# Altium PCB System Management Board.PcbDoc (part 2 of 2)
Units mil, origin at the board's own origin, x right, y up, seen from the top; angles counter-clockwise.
Board outline 5905.51 x 4330.71 mil, 4 copper layers (F.Cu, In1.Cu, In2.Cu, B.Cu); 241 components, 148 nets, 704 pads, 16 vias.
Unrouted connection lines stored in the file: 314.
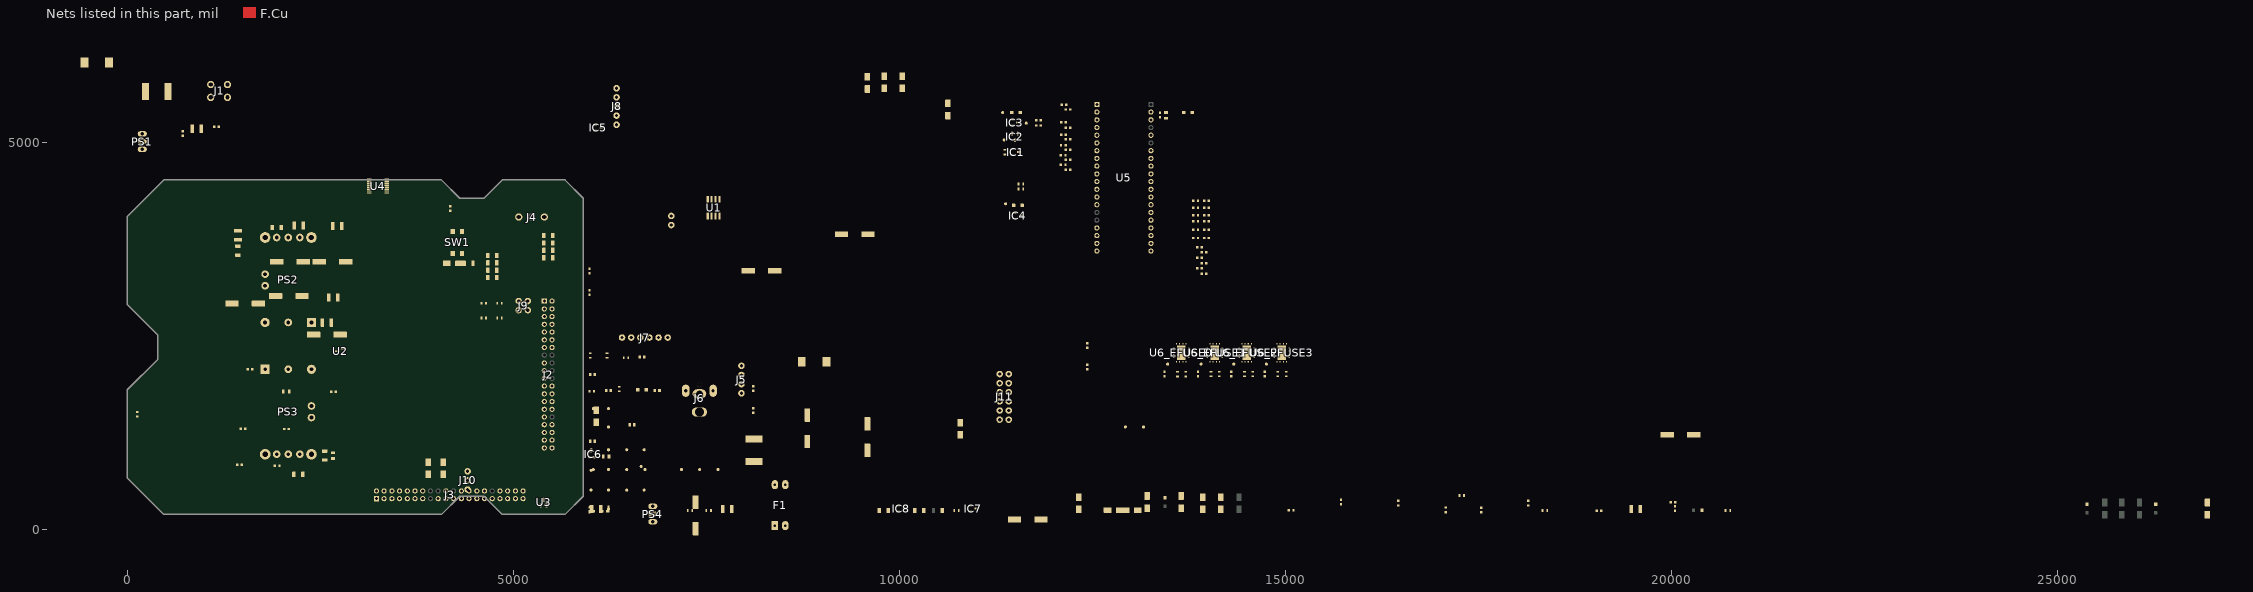
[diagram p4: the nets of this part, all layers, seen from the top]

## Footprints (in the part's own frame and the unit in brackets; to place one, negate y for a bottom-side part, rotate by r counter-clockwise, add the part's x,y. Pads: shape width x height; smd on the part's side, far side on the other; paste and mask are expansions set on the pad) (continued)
PINHEADER_2X20_P2.54MM_HORIZONTAL [mm]
  rect 1.7x1.7 hole 1 paste-2539.97 mask+0: 1(0,0)
  rrect100% 1.7x1.7 hole 1 paste-2539.97 mask+0: 2(2.54,0) 3(0,-2.54) 4(2.54,-2.54) 5(0,-5.08) 6(2.54,-5.08) 7(0,-7.62) 8(2.54,-7.62) 9(0,-10.16) 10(2.54,-10.16) 11(0,-12.7) 12(2.54,-12.7) 13(0,-15.24) 14(2.54,-15.24) 15(0,-17.78) 16(2.54,-17.78) 17(0,-20.32) 18(2.54,-20.32) 19(0,-22.86) 20(2.54,-22.86) 21(0,-25.4) 22(2.54,-25.4) 23(0,-27.94) 24(2.54,-27.94) 25(0,-30.48) 26(2.54,-30.48) 27(0,-33.02) 28(2.54,-33.02) 29(0,-35.56) 30(2.54,-35.56) 31(0,-38.1) 32(2.54,-38.1) 33(0,-40.64) 34(2.54,-40.64) 35(0,-43.18) 36(2.54,-43.18) 37(0,-45.72) 38(2.54,-45.72) 39(0,-48.26) 40(2.54,-48.26)
  silkscreen extent -1.27,-49.59 12.64,1.33, body extent -1.14,-59.18 22.16,10.92, height 8.5
PinHeader_2x20_P2.54mm_Vertical [mm]
  rect 1.7x1.7 hole 1 paste-2539.97 mask+0: 1(0,0)
  rrect100% 1.7x1.7 hole 1 paste-2539.97 mask+0: 2(2.54,0) 3(0,-2.54) 4(2.54,-2.54) 5(0,-5.08) 6(2.54,-5.08) 7(0,-7.62) 8(2.54,-7.62) 9(0,-10.16) 10(2.54,-10.16) 11(0,-12.7) 12(2.54,-12.7) 13(0,-15.24) 14(2.54,-15.24) 15(0,-17.78) 16(2.54,-17.78) 17(0,-20.32) 18(2.54,-20.32) 19(0,-22.86) 20(2.54,-22.86) 21(0,-25.4) 22(2.54,-25.4) 23(0,-27.94) 24(2.54,-27.94) 25(0,-30.48) 26(2.54,-30.48) 27(0,-33.02) 28(2.54,-33.02) 29(0,-35.56) 30(2.54,-35.56) 31(0,-38.1) 32(2.54,-38.1) 33(0,-40.64) 34(2.54,-40.64) 35(0,-43.18) 36(2.54,-43.18) 37(0,-45.72) 38(2.54,-45.72) 39(0,-48.26) 40(2.54,-48.26)
  silkscreen extent -1.33,-49.59 3.87,1.33
R_0603 [mm]
  rect 0.6x0.9 smd: 1(-0.75,0) 2(0.75,0)
  silkscreen extent -1.3,-0.7 1.3,0.7, body extent -0.8,-0.4 0.75,0.4, height 0.44
R_1206_3216Metric [mm]
  rrect22% 1.125x1.75 smd mask+0: 1(-1.462,0) 2(1.462,0)
  silkscreen extent -0.73,-0.91 0.73,0.91
R_1206_3216METRIC [mm]
  rrect22% 1.125x1.75 smd mask+0: 1(-1.462,0) 2(1.462,0)
  silkscreen extent -0.73,-0.91 0.73,0.91
SMAZ36-13-F [mm]
  rect 2.5x1.7 smd: A(-2,0) K(2,0)
  silkscreen extent -3.9,-1.1 3.5,1.1, body extent -2.6,-1.3 2.6,1.3, height 2.4
SOT95P237X112-3N [mm]
  rect 1.3x0.6 smd: 1(-1.05,0.95) 2(-1.05,-0.95) 3(1.05,0)
  silkscreen extent -1.7,-1.46 0.05,1.5
SOT-23 [mm]
  rrect25% 1.475x0.6 smd mask+0: 1(-0.937,0.95) 2(-0.937,-0.95) 3(0.937,0)
  silkscreen extent -1.68,-1.56 0.65,1.56
SW_TL3305BF260QG [mm]
  rect 1.6x1.4 smd mask+0: 1(-3.6,-1.5) 1(3.6,-1.5) 2(-3.6,1.5) 2(3.6,1.5)
  silkscreen extent -5.1,-2.25 2.25,2.25, body extent -3.72,-2.25 3.78,2.25, height 5
TestPoint_Pad_D1.0mm [mm]
  round 1 smd paste-1 mask+0: 1(0,0)
  silkscreen extent -0.7,-0.7 0.7,0.7
TSSOP-16_4.4x5mm_P0.65mm [mm]
  rrect25% 1.475x0.4 smd mask+0: 1(-2.863,2.275) 2(-2.863,1.625) 3(-2.863,0.975) 4(-2.863,0.325) 5(-2.863,-0.325) 6(-2.863,-0.975) 7(-2.863,-1.625) 8(-2.863,-2.275) 9(2.863,-2.275) 10(2.863,-1.625) 11(2.863,-0.975) 12(2.863,-0.325) 13(2.863,0.325) 14(2.863,0.975) 15(2.863,1.625) 16(2.863,2.275)
  silkscreen extent -3.6,-2.74 2.2,2.74

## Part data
C1: "Ceramic Capacitor, Multilayer, Ceramic, 63V, 10% +Tol, 10% -Tol, X7R, 15% TC, 10uF, Surface Mount, 1210", Capacitor Type=Ceramic, Case/Package=1210, Manufacturer=Samsung, Manufacturer Part Number=CL32B106KMVNNWE, Max Operating Temperature=125°C, Min Operating Temperature=-55°C, Package Shape=Rectangular, Rated DC Voltage (URdc)=63V, Supplier Part Number=1276-7053-1-ND, Temperature Characteristics Code=X7R, Tolerance  (fill in as +-)=10%
C2 C4 C25 C26 C27 C28 C29 C31 C33 C34: "Ceramic Capacitor, Multilayer, Ceramic, 100V, 10% +Tol, 10% -Tol, X7R, 15% TC, 0.1uF, Surface Mount, 0603", Capacitor Type=Ceramic, Case/Package=0603, Manufacturer=Samsung, Max Operating Temperature=125°C, Min Operating Temperature=-55°C, Package Shape=Rectangular, Rated DC Voltage (URdc)=100V, Supplier Part Number=1276-6807-1-ND, Temperature Characteristics Code=X7R, Tolerance  (fill in as +-)=10%
C3 C30 C32 C35: "Ceramic Capacitor, Multilayer, Ceramic, 10V, 10% +Tol, 10% -Tol, X7R, 15% TC, 10uF, Surface Mount, 0805", Capacitor Type=Ceramic, Case/Package=0805, Manufacturer=Samsung, Max Operating Temperature=125°C, Min Operating Temperature=-55°C, Package Shape=Rectangular, Rated DC Voltage (URdc)=10V, Supplier Part Number=1276-2934-1-ND, Temperature Characteristics Code=X7R, Tolerance  (fill in as +-)=10%
C5 C9 C10 C14 C15 C19 C20 C24: library part C, "Ceramic Capacitor, Multilayer, Ceramic, 63V, 10% +Tol, 10% -Tol, X7R, 15% TC, 10uF, Surface Mount, 1210", Capacitor Type=Ceramic, Case/Package=1210, Manufacturer=Samsung, Manufacturer Part Number=CL32B106KMVNNWE, Max Operating Temperature=125°C, Min Operating Temperature=-55°C, Package Shape=Rectangular, Rated DC Voltage (URdc)=63V, Supplier Part Number=1276-7053-1-ND, Temperature Characteristics Code=X7R, Tolerance  (fill in as +-)=10%
C6 C7 C8 C11 C12 C13 C16 C17 C18 C21 C22 C23: library part C_Polarized, Voltage=63V
D1 D2 D10_EFUSE0 D10_EFUSE1 D10_EFUSE2 D10_EFUSE3 D28: "Led Red Diffused 0603 SMD", Manufacturer=Inolux, Supplier Part Number=3147-B1931USD-20D000814U1930CT-ND
D3 D4 D5 D26: "Led Green Diffused 0603 SMD", Manufacturer=Inolux, Supplier Part Number=3147-B1931NG--20D001114U1930CT-ND
D6 D7: library part D
D8 D9 D23 D24 D25 D32: library part D, "Rectifier Diode, Schottky, 1 Phase, 1 Element, 1A, 40V V(RRM), Silicon", Manufacturer=MCC, Manufacturer Part Number=SM5819PL-TP, Max Operating Temperature=125°C, Max Output current=1A, Max Power Dissipation=1.14W, Min Operating Temperature=-65°C, Non-rep Pk Forward Current-Max=30A, Package Body Material=Plastic, Package Shape=Rectangular, Package Style="SMALL OUTLINEMeter", Peak Reflow Temperature (Cel)=260°C, Rep Pk Reverse Voltage-Max=40V, Supplier Part Number=SM5819PL-TPMSCT-ND, Time @ Peak Reflow Temperature-Max (s)=10s
D12 D13 D14 D15 D16 D17 D18 D19 D30 D33 D34 D35 D36 D37 D38 D39: library part D_TVS, "Trans Voltage Suppressor Diode, 400W, 51V V(RWM), Bidirectional, 1 Element, Silicon, DO-214AC", Breakdown Voltage-Nom=59.7V, Clamping Voltage-Max=82.4V, Manufacturer=Littelfuse, Manufacturer Part Number=SMAJ51CA, Max Breakdown Voltage=62.7V, Max Operating Temperature=150°C, Min Breakdown Voltage=56.7V, Min Operating Temperature=-65°C, Non-rep Peak Rev Power Dis-Max=400W, Package Body Material=Plastic, Package Shape=Rectangular, Package Style="SMALL OUTLINEMeter", Peak Reflow Temperature (Cel)=260°C, Rep Pk Reverse Voltage-Max=51V, Supplier Part Number=SMAJ51CALFCT-ND, Time @ Peak Reflow Temperature-Max (s)=40s
D20 D21 D22 D31: "Zener Diode, 36V V(Z), 5%, 1W, Silicon, Unidirectional", Manufacturer=Diodes, Max Operating Temperature=150°C, Max Power Dissipation=1W, Min Operating Temperature=-65°C, Package Body Material=Plastic, Package Shape=Rectangular, Package Style="SMALL OUTLINEMeter", Peak Reflow Temperature (Cel)=260°C, Reference Voltage-Nom=36V, Supplier Part Number=SMAZ36-FDICT-ND, Test Current=10mA, Time @ Peak Reflow Temperature-Max (s)=40s, Voltage Tol-Max=5%
D27: "Led Yellow Clear 1608 SMD", Manufacturer=Inolux, Supplier Part Number=3147-B1931UY--20D000114U1930CT-ND
D29: "Led Blue Clear 1608 SMD", Manufacturer=Inolux, Supplier Part Number=3147-B1931NB--20C007614U1930CT-ND
F1: library part 3557-10, "Holder; Fuse; Auto Blade; 30A; PC Pin Terminal; Nylon Holder; Red", Manufacturer="Keystone Electronics", Supplier Part Number=36-3557-10-ND
F2 F10: "PTC Resettable Fuse, 33V, 0.04ohm, Surface Mount", Manufacturer=Bel, Max Operating Temperature=85°C, Min Operating Temperature=-40°C, Package Shape=Rectangular, Power=1.5W, Resistor Type="PTC THERMISTOR", Supplier Part Number=5923-0ZCF0185FF2CCT-ND
F3 F4: library part Fuse, "Fuse Chip Medium Time Delay Acting 25A 250V SMD Solder Pad 3912 9.8 X 3.05 X 4.06mm Ceramic", Case/Package=SMD/SMT, DC Cold Resistance=1.9mR, Manufacturer=Bel, Manufacturer Part Number=0678L9250-02, Max Operating Temperature=125°C, Min Operating Temperature=-55°C, Supplier Part Number=5923-0678L9250-02CT-ND, Voltage Rating (AC)=250V, Voltage Rating (DC)=72V
F5 F6 F7: "Electric Fuse, Fast Blow, 0.1A, 32VAC, 32VDC, Surface Mount", Current Rating=100mA, Manufacturer="Kyocera AVX", Max Operating Temperature=125°C, Min Operating Temperature=-55°C, Supplier Part Number=478-6872-1-ND
F8 F9 F11: library part F0603E0R50FSTR, "Electric Fuse, Fast Blow, 0.5A, 32VAC, 32VDC, 50A (IR), Surface Mount, 0603", Current Rating=500mA, Manufacturer="Kyocera AVX", Manufacturer Series=F0603E, Supplier Part Number=478-2860-1-ND, Voltage Rating (AC)=32V
IC1 IC2 IC3 IC4: "Small Signal Field-Effect Transistor, 5.6A I(D), 40V, 1-Element, N-Channel, Silicon, Metal-oxide Semiconductor FET, TO-236AB", Drain Current-Max (Abs) (ID)=5.6A, Drain-source On Resistance-Max=42mR, DS Breakdown Voltage-Min=40V, Manufacturer="Vishay Siliconix", MANUFACTURER_NAME=Vishay, Max Operating Temperature=150°C, Min Operating Temperature=-55°C, Operating Mode="ENHANCEMENT MODE", Package Body Material=Plastic, Package Shape=Rectangular, Package Style="SMALL OUTLINEMeter", Peak Reflow Temperature (Cel)=260°C, Power Dissipation-Max (Abs)=2.1W, Supplier Part Number=SI2318CDS-T1-GE3CT-ND, Time @ Peak Reflow Temperature-Max (s)=30s
IC5 IC6 IC7 IC8: library part SI2318CDS-T1-GE3, "Small Signal Field-Effect Transistor, 5.6A I(D), 40V, 1-Element, N-Channel, Silicon, Metal-oxide Semiconductor FET, TO-236AB", Drain Current-Max (Abs) (ID)=5.6A, Drain-source On Resistance-Max=42mR, DS Breakdown Voltage-Min=40V, Manufacturer="Vishay Siliconix", MANUFACTURER_NAME=Vishay, Max Operating Temperature=150°C, Min Operating Temperature=-55°C, Operating Mode="ENHANCEMENT MODE", Package Body Material=Plastic, Package Shape=Rectangular, Package Style="SMALL OUTLINEMeter", Peak Reflow Temperature (Cel)=260°C, Power Dissipation-Max (Abs)=2.1W, Supplier Part Number=SI2318CDS-T1-GE3CT-ND, Time @ Peak Reflow Temperature-Max (s)=30s
J1: "Rectangular Power Connector, 4 Contact(s), Male, Solder Terminal, Plug", Contact Resistance=10mR, Dielectric Withstanding Voltage (AC)=1.5kV, Flammability Rating="UL94 V-2", Insulation Resistance=1GR, Manufacturer=Molex, Max Operating Temperature=105°C, Min Operating Temperature=-40°C, Rated Current (Signal)=8A, Supplier Part Number=WM3844-ND
J2 J3: library part Conn_02x20_Odd_Even
J4: "Rectangular Power Connector, 3 Contact(s), Male, Solder Terminal, Plug", Contact Resistance=10mR, Dielectric Withstanding Voltage (AC)=1.5kV, Flammability Rating="UL94 V-2", Insulation Resistance=1GR, Manufacturer=Molex, Manufacturer Series=5566, Max Operating Temperature=105°C, Min Operating Temperature=-40°C, Rated Current (Signal)=9A, Supplier Part Number=WM18442-ND
J5: "Rectangular Power Connector, 4 Contact(s), Female, Solder Terminal", Contact Resistance=10mR, Dielectric Withstanding Voltage (AC)=1.5kV, Flammability Rating="UL94 V-0", Insulation Color=Black, Insulation Resistance=1GR, Manufacturer=Molex, Manufacturer Series=43650, Max Operating Temperature=105°C, Min Operating Temperature=-40°C, Rated Current (Signal)=5A, Supplier Part Number=WM10669-ND
J6: library part PJ-063BH, "Circular DC Power Connector, 24V, 8A, 2.5mm Dia", Manufacturer="CUI INC", Supplier Part Number=CP-063BH-ND
J7: "Rectangular Power Connector, 6 Contact(s), Female, Solder Terminal", Contact Resistance=10mR, Dielectric Withstanding Voltage (AC)=1.5kV, Flammability Rating="UL94 V-0", Insulation Color=Black, Insulation Resistance=1GR, Manufacturer=Molex, Manufacturer Series=43650, Max Operating Temperature=105°C, Min Operating Temperature=-40°C, Rated Current (Signal)=5A, Supplier Part Number=WM17059-ND
J8: "Rectangular Power Connector, 5 Contact(s), Female, Solder Terminal", Contact Resistance=10mR, Dielectric Withstanding Voltage (AC)=1.5kV, Flammability Rating="UL94 V-0", Insulation Color=Black, Insulation Resistance=1GR, Manufacturer=Molex, Max Operating Temperature=105°C, Min Operating Temperature=-40°C, Rated Current (Signal)=5A, Supplier Part Number=WM10666-ND
J9: "Board Connector, 4 Contact(s), 2 Row(s), Male, Straight, Solder Terminal, Locking, Black Insulator, Receptacle", Contact Resistance=10mR, Flammability Rating="UL94 V-0", Insulation Color=Black, Insulation Resistance=1GR, Manufacturer=Molex, Max Operating Temperature=105°C, Min Operating Temperature=-40°C, Rated Current (Signal)=2.5A, Supplier Part Number=WM10670-ND
J10: "Rectangular Power Connector, 3 Contact(s), Female, Solder Terminal", Contact Resistance=10mR, Dielectric Withstanding Voltage (AC)=1.5kV, Flammability Rating="UL94 V-0", Insulation Color=Black, Insulation Resistance=1GR, Manufacturer=Molex, Manufacturer Series=43650, Max Operating Temperature=105°C, Min Operating Temperature=-40°C, Rated Current (Signal)=5A, Supplier Part Number=WM10661-ND
J11: "Board Connector, 12 Contact(s), 2 Row(s), Male, Straight, Solder Terminal, Locking, Black Insulator, Receptacle", Contact Resistance=10mR, Flammability Rating="UL94 V-0", Insulation Color=Black, Insulation Resistance=1GR, Manufacturer=Molex, Max Operating Temperature=105°C, Min Operating Temperature=-40°C, Rated Current (Signal)=2.5A, Supplier Part Number=WM10705-ND
J12: "Rectangular Power Connector, 2 Contact(s), Female, Solder Terminal", Contact Resistance=10mR, Dielectric Withstanding Voltage (AC)=1.5kV, Flammability Rating="UL94 V-0", Insulation Color=Black, Insulation Resistance=1GR, Manufacturer=Molex, Manufacturer Series=43650, Max Operating Temperature=105°C, Min Operating Temperature=-40°C, Rated Current (Signal)=5A, Supplier Part Number=WM10658-ND
PS1: "DC-DC Regulated Power Supply Module, 1 Output, 7.8W, Hybrid", Manufacturer=Murata, Max Output Power=7.8W, Max Output Voltage=5.2V, Max Supply Voltage=36V, Min Input Voltage=7V, Min Output Voltage=4.8V, Nominal Output Voltage=5V, Nominal Supply Voltage=12V, Package Shape=Rectangular, Supplier Part Number=811-3292-ND
PS2 PS3: library part I7C4W008A120V-0C3-R, Manufacturer=TDK, MAXIMUM_PACKAGE_HEIGHT="13.5 mm"
PS4: "DC-DC Regulated Power Supply Module, 1 Output, 5.15W, Hybrid", Manufacturer=Murata, Max Output Power=5.15W, Max Output Voltage=3.432V, Max Supply Voltage=36V, Min Input Voltage=7V, Min Output Voltage=3.168V, Nominal Output Voltage=3.3V, Nominal Supply Voltage=12V, Package Shape=Rectangular, Supplier Part Number=580-78SR3.3/1.5W36EC
R1: "Fixed Resistor, Thin Film, 0.166W, 4640ohm, 100V, 0.1% +/-Tol, 25ppm/Cel, Surface Mount, 0603", Case/Package=0603, Manufacturer="Stackpole Electronics", Max Operating Temperature=155°C, Min Operating Temperature=-55°C, Package Height=0.45mm, Package Length=1.55mm, Package Shape=Rectangular, Package Width=0.8mm, Power=166mW, Rated Temperature=70°C, Resistor Type="FIXED RESISTOR", Supplier Part Number=738-RNCF0603BTE4K64CT-ND, Temperature Coefficient (ppm/Cel)=25, Tolerance=0.1%, Working Voltage=100V
R2 R5: "Fixed Resistor, Metal Glaze/thick Film, 0.1W, 1000ohm, 75V, 1% +/-Tol, 100ppm/Cel, Surface Mount, 0603", Case/Package=0603, Manufacturer="Stackpole Electronics", Max Operating Temperature=155°C, Min Operating Temperature=-55°C, Package Height=0.45mm, Package Length=1.55mm, Package Shape=Rectangular, Package Width=0.8mm, Power=100mW, Rated Temperature=70°C, Resistor Type="FIXED RESISTOR", Supplier Part Number=RMCF0603FG1K00CT-ND, Temperature Coefficient (ppm/Cel)=100, Tolerance=1%, Working Voltage=75V
R3 R6 R33 R34 R35 R36 R37 R38 R39 R40 R42 R43 R44 R45 R46 R47 R48 R49 R50 R51 R52 R53 R55 R56 R59 R60 R61 R62 R64 R65 R66 R67 R69 R70 R72_EFUSE0 R72_EFUSE1 R72_EFUSE2 R72_EFUSE3 R75 R76 R77 R78: "Fixed Resistor, Metal Glaze/thick Film, 0.1W, 2000ohm, 75V, 1% +/-Tol, 100ppm/Cel, Surface Mount, 0603", Case/Package=0603, Manufacturer="Stackpole Electronics", Max Operating Temperature=155°C, Min Operating Temperature=-55°C, Package Height=0.45mm, Package Length=1.55mm, Package Shape=Rectangular, Package Width=0.8mm, Power=100mW, Rated Temperature=70°C, Resistor Type="FIXED RESISTOR", Supplier Part Number=RMCF0603FT2K00CT-ND, Temperature Coefficient (ppm/Cel)=100, Tolerance=1%, Working Voltage=75V
R4: "Fixed Resistor, Metal Glaze/thick Film, 0.1W, 28ohm, 75V, 1% +/-Tol, 100ppm/Cel, Surface Mount, 0603", Case/Package=0603, Manufacturer="Stackpole Electronics", Max Operating Temperature=155°C, Min Operating Temperature=-55°C, Package Height=0.45mm, Package Length=1.55mm, Package Shape=Rectangular, Package Width=0.8mm, Power=100mW, Rated Temperature=70°C, Resistor Type="FIXED RESISTOR", Supplier Part Number=738-RMCF0603FT28R0CT-ND, Temperature Coefficient (ppm/Cel)=100, Tolerance=1%, Working Voltage=75V
R7 R8 R9 R10 R16 R41 R54 R63: "Fixed Resistor, Metal Glaze/thick Film, 0.1W, 10000ohm, 75V, 1% +/-Tol, 100ppm/Cel, Surface Mount, 0603", Case/Package=0603, Manufacturer="Stackpole Electronics", Max Operating Temperature=155°C, Min Operating Temperature=-55°C, Package Height=0.45mm, Package Length=1.55mm, Package Shape=Rectangular, Package Width=0.8mm, Power=100mW, Rated Temperature=70°C, Resistor Type="FIXED RESISTOR", Supplier Part Number=RMCF0603FT10K0CT-ND, Temperature Coefficient (ppm/Cel)=100, Tolerance=1%, Working Voltage=75V
R11 R12 R13 R14 R15: "Fixed Resistor, Metal Glaze/thick Film, 0.1W, 10ohm, 75V, 1% +/-Tol, 100ppm/Cel, Surface Mount, 0603", Case/Package=0603, Manufacturer="Stackpole Electronics", Max Operating Temperature=155°C, Min Operating Temperature=-55°C, Package Height=0.45mm, Package Length=1.55mm, Package Shape=Rectangular, Package Width=0.8mm, Power=100mW, Rated Temperature=70°C, Resistor Type="FIXED RESISTOR", Supplier Part Number=RMCF0603FT10R0CT-ND, Temperature Coefficient (ppm/Cel)=100, Tolerance=1%, Working Voltage=75V
R17 R18 R19 R20 R21 R22 R23 R24 R25 R26 R27 R28 R29 R30 R31 R32: library part R
R57 R58 R74_EFUSE0 R74_EFUSE1 R74_EFUSE2 R74_EFUSE3: "Fixed Resistor, Metal Glaze/thick Film, 0.1W, 0ohm, Surface Mount, 0603", Case/Package=0603, Manufacturer="Stackpole Electronics", Max Operating Temperature=155°C, Min Operating Temperature=-55°C, Package Height=0.45mm, Package Length=1.55mm, Package Shape=Rectangular, Package Width=0.8mm, Power=100mW, Rated Temperature=70°C, Resistor Type="FIXED RESISTOR", Supplier Part Number=RMCF0603ZT0R00CT-ND, Working Voltage=75V
R68: "Fixed Resistor, Metal Glaze/thick Film, 0.1W, 220000ohm, 75V, 1% +/-Tol, 100ppm/Cel, Surface Mount, 0603", Case/Package=0603, Manufacturer="Stackpole Electronics", Max Operating Temperature=155°C, Min Operating Temperature=-55°C, Package Height=0.45mm, Package Length=1.55mm, Package Shape=Rectangular, Package Width=0.8mm, Power=100mW, Rated Temperature=70°C, Resistor Type="FIXED RESISTOR", Supplier Part Number=RMCF0603FT220KCT-ND, Temperature Coefficient (ppm/Cel)=100, Tolerance=1%, Working Voltage=75V
R71 R73_EFUSE0 R73_EFUSE1 R73_EFUSE2 R73_EFUSE3: "Fixed Resistor, Metal Glaze/thick Film, 0.1W, 30000ohm, 75V, 1% +/-Tol, 100ppm/Cel, Surface Mount, 0603", Case/Package=0603, Manufacturer="Stackpole Electronics", Max Operating Temperature=155°C, Min Operating Temperature=-55°C, Package Height=0.45mm, Package Length=1.55mm, Package Shape=Rectangular, Package Width=0.8mm, Power=100mW, Rated Temperature=70°C, Resistor Type="FIXED RESISTOR", Supplier Part Number=RMCF0603FT30K0CT-ND, Temperature Coefficient (ppm/Cel)=100, Tolerance=1%, Working Voltage=75V
SW1: library part SW_Push_4_PIN_1, "Keypad Switch, 1 Switches, SPST, Momentary, 0.05A, 12VDC, 3.04N, Solder Terminal, Surface Mount-straight", Contact Current(DC)-Max=50mA, Contact DC Max Rating R Load=.05A@12VDC, Contact Voltage(DC)-Max=12V, Manufacturer=E-Switch, Manufacturer Part Number=TL3305BF260QG, Max Operating Temperature=70°C, Min Operating Temperature=-20°C, Operating Force-Max=3.04N, Supplier Part Number=EG5354CT-ND
TP15 TP16 TP17 TP18 TP19 TP20 TP21 TP22 TP23 TP24 TP25 TP26 TP27 TP28 TP29 TP30 TP31 TP32 TP33 TP34 TP35 TP36 TP37 TP38 TP39 TP40 TP41 TP42 TP43_EFUSE0 TP43_EFUSE1 TP43_EFUSE2 TP43_EFUSE3: library part TestPoint_1
U1: library part THVD1450DR, Case/Package=SOP, Manufacturer="Texas Instruments", Max Operating Temperature=125°C, Max Supply Voltage=5.5V, Min Operating Temperature=-40°C, Min Supply Voltage=3V, Nominal Supply Voltage=5V, Package Body Material=Plastic, Package Shape=Rectangular, Package Style="SMALL OUTLINEMeter", Supplier Part Number=296-50395-1-ND, Supplier Part Number 1=ISL32495EIBZ-ND, Temperature Grade=AUTOMOTIVE
U2 U3: library part MCP9700T-ETT
U4: library part 74HC4051
U5: "Raspberry Pi Pico Embedded Dev Module", Manufacturer="Raspberry Pi", MAXIMUM_PACKAGE_HEIGHT=3.73mm, Supplier Part Number=2648-SC0915CT-ND
U6_EFUSE0 U6_EFUSE1 U6_EFUSE2 U6_EFUSE3: "Electronic fuse (eFuse) 4-channel, 8V to 60V, 10A in 5x6mm package Latch version", Manufacturer=onsemi, Supplier Part Number=488-NIV3071MTW3TWGCT-ND

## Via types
v1: diameter 59.06, hole 59.06, F.Cu to B.Cu, tented both sides, 14 vias
v2: diameter 125.98, hole 125.98, F.Cu to B.Cu, tented both sides, 2 vias

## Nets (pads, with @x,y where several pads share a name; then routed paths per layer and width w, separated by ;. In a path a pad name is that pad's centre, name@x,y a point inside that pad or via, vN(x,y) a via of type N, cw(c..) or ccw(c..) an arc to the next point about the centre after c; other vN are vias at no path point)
"15V CM": C14.1 R2.2 R22.1 TP21.1
15V_MES_ADC: R19.1 R25.1 R27.1 TP29.1
24V_MES_ADC: R18.1 R30.1 R32.1 TP32.1
"48V POE EF EN": U6_EFUSE0.13 U6_EFUSE0.14 U6_EFUSE0.15 U6_EFUSE0.16 U6_EFUSE1.15 U6_EFUSE1.16
48V_AUX_EF_EN: R39.1 R40.1 U5.5 U6_EFUSE1.14
48V_MES_ADC: R20.1 R29.1 R31.1 TP31.1
48V_POE_EF_EN: R37.1 R38.1 U5.4 | length 4.5
  F.Cu w9.84: R38.1@12152.36,5268.9 R38.1@12155.51,5265.75
+3V3: C34.1 C35.1 D6.1 D10_EFUSE0.1 D10_EFUSE1.1 D10_EFUSE2.1 D10_EFUSE3.1 F6.1 F7.1 PS4.3 R3.1 R6.1 R34.2 R36.2 R38.2 R40.2 R43.2 R45.2 R47.2 R49.2 R51.2 R53.2 R56.2 R60.2 R62.2 R65.2 R67.2 R70.2 TP42.1
+5V: C3.1 C4.1 F5.1 F8.1 F11.2 PS1.3 R26.2 TP18.1
+15V: C5.1 C6.1 C7.1 C8.1 D4.1 PS2.7 PS2.8 R25.2 TP20.1 U6_EFUSE3.2 U6_EFUSE3.3 U6_EFUSE3.11
+24_VIN: D11.2 F1.1 F1.2 J1.1 J1.3 TP16.1
+24V: D3.1 F1.3 F1.4 F2.1 F3.1 F4.1 F10.1 R30.2 TP17.1 U6_EFUSE1.10 U6_EFUSE2.2 U6_EFUSE2.3 U6_EFUSE2.10 U6_EFUSE2.11 U6_EFUSE3.10
+48V: C15.1 C16.1 C17.1 C18.1 D5.1 PS3.7 PS3.8 R29.2 TP24.1 U6_EFUSE0.2 U6_EFUSE0.3 U6_EFUSE0.10 U6_EFUSE0.11 U6_EFUSE1.2 U6_EFUSE1.3 U6_EFUSE1.11
+48V_PWR_EN: IC1.1 R35.1 R36.1 R41.1 U5.1
\1\5\V\_\J\E\T\S\O\N\_\E\N\: D8.2 U5.2
\+\1\5\_\P\W\R\_\E\N\: IC2.3 PS2.2 TP36.1
\+\4\8\_\P\W\R\_\E\N\: IC1.3 PS3.2 TP35.1
\N\T\W\K\_\S\W\I\T\C\H\_\E\F\_\E\N\: D9.2 U5.14
\P\I\C\O\_\R\E\S\E\T\: C29.2 J2.13 J3.13 SW1.2 TP33.1 U5.30
BLUE_EN: D29.1 IC8.1 R69.1 R70.1 U5.27
BLUE_LED_LOWSIDE: IC8.3 J8.5
CONTACTOR_CTRL_1: R42.1 R43.1 U5.6 U6_EFUSE2.16
CONTACTOR_CTRL_2: R44.1 R45.1 U5.7 U6_EFUSE2.15
CONTACTOR_CTRL_3: R46.1 R47.1 U5.9 U6_EFUSE2.14
CONTACTOR_CTRL_4: R48.1 R49.1 U5.10 U6_EFUSE2.13
CONTACTOR_OUT_1: D30.2 J9.1 J9.3 U6_EFUSE2.1
CONTACTOR_OUT_2: D17.2 J7.1 U6_EFUSE2.4
CONTACTOR_OUT_3: D18.2 J7.3 U6_EFUSE2.12
CONTACTOR_OUT_4: D19.2 J7.5 U6_EFUSE2.9
CPS_IN_PROT: C9.1 C10.1 C11.1 C12.1 C13.1 F3.2 PS2.1 TP19.1
EN1_EFUSE3: IC2.1 IC3.3 R33.1 R34.1 TP37.1 U6_EFUSE3.14 U6_EFUSE3.15 U6_EFUSE3.16
EN4_EFUSE1: IC4.3 R52.1 R53.1 TP39.1 U6_EFUSE1.13
EN4_EFUSE3: R50.1 R51.1 U6_EFUSE3.13
ESTOP_SENSE: J10.1 R55.1 R56.1 R68.1
ESTOP_SENSE_MCU: R68.2 R71.1 U5.32
ESTOP_TRIG: J10.2 R59.1 R60.1 U5.34
GND: C1.2 C2.2 C3.2 C4.2 C5.2 C6.2 C7.2 C8.2 C9.2 C10.2 C11.2 C12.2 C13.2 C14.2 C15.2 C16.2 C17.2 C18.2 C19.2 C20.2 C21.2 C22.2 C23.2 C24.2 C25.2 C26.2 C27.2 C28.2 C29.1 C30.2 C31.2 C32.2 C33.2 C34.2 C35.2 D1.2 D2.2 D11.1 D12.1 D13.1 D14.1 D15.1 D16.1 D17.1 D18.1 D19.1 D23.2 D24.2 D25.2 D30.1 D32.2 D33.1 D34.1 D35.1 D36.1 D37.1 D38.1 D39.1 F9.2 IC1.2 IC2.2 IC3.2 IC4.2 IC5.2 IC6.2 IC7.2 IC8.2 J1.2 J1.4 J2.6 J2.9 J2.14 J2.24 J2.25 J2.30 J2.34 J2.39 J3.6 J3.9 J3.14 J3.20 J3.24 J3.25 J3.30 J3.34 J3.39 J4.3 J6.2 J6.S1 J6.S2 J7.2 J7.4 J7.6 J9.2 J9.4 J10.3 J11.2 J11.4 J11.6 J11.8 J11.10 J11.12 J12.2 PS1.2 PS2.3 PS2.4 PS2.32 PS3.3 PS3.4 PS3.32 PS4.2 R1.2 R4.2 R7.2 R8.2 R9.2 R16.2 R27.2 R28.2 R31.2 R32.2 R33.2 R35.2 R37.2 R39.2 R41.2 R42.2 R44.2 R46.2 R48.2 R50.2 R52.2 R54.2 R55.2 R59.2 R61.2 R63.2 R64.2 R66.2 R69.2 R71.2 R73_EFUSE0.2 R73_EFUSE1.2 R73_EFUSE2.2 R73_EFUSE3.2 R74_EFUSE0.2 R74_EFUSE1.2 R74_EFUSE2.2 R74_EFUSE3.2 R75.1 R76.1 R77.1 R78.1 SW1.1 U1.5 U2.3 U3.3 U4.6 U4.7 U4.8 U6_EFUSE0.8 U6_EFUSE0.17 U6_EFUSE1.8 U6_EFUSE1.17 U6_EFUSE2.8 U6_EFUSE2.17 U6_EFUSE3.8 U6_EFUSE3.17
GREEN_EN: D26.1 IC5.1 R61.1 R62.1 U5.17
GREEN_LED_LOWSIDE: IC5.3 J8.2
JET_P1: J2.1 J3.1
JET_P2: J2.2 J3.2
JET_P3: J2.3 J3.3
JET_P4: J2.4 J3.4
JET_P5: J2.5 J3.5
JET_P7: J2.7 J3.7
JET_P11: J2.11 J3.11
JET_P12: J2.12 J3.12
JET_P17: J2.17 J3.17
JET_P19: J2.19 J3.19
JET_P21: J2.21 J3.21
JET_P23: J2.23 J3.23
JET_P26: J2.26 J3.26
JET_P27: J2.27 J3.27
JET_P28: J2.28 J3.28
JET_P29: J2.29 J3.29
JET_P31: J2.31 J3.31
JET_P33: J2.33 J3.33
JET_P35: J2.35 J3.35
JET_P36: J2.36 J3.36
JET_P37: J2.37 J3.37
JET_P38: J2.38 J3.38
JET_P40: J2.40 J3.40
Jet_UART1_Rx: R57.2 U5.11
Jet_UART1_Rx_IN: J2.10 J3.10 R58.1
Jet_UART1_Tx: R58.2 U5.12
Jet_UART1_Tx_IN: J2.8 J3.8 R57.1
"JETSON OUT": D13.2 J6.1 U6_EFUSE3.1 U6_EFUSE3.4 U6_EFUSE3.12
MUX_IN: U4.3 U5.31
MUX_S0: U4.11 U5.24
MUX_S1: U4.10 U5.25
MUX_S2: U4.9 U5.26
NetC1_1: C1.1 C2.1 F2.2 PS1.1 TP15.1
NetC25_1: C25.1 F5.2 R10.1
NetC26_1: C26.1 U1.8
NetC27_1: C27.1 F6.2 U2.1 U3.1
NetC28_1: C28.1 F7.2 U4.16
NetC32_1: C32.1 C33.1 F10.2 PS4.1 TP41.1
NetD1_1: D1.1 PS2.5 R3.2 TP22.1
NetD2_1: D2.1 PS3.5 R6.2 TP26.1
NetD3_2: D3.2 R7.1
NetD4_2: D4.2 R8.1
NetD5_2: D5.2 R9.1
NetD7_2: D7.2 F8.2
NetD8_1: D8.1 IC3.1 R54.1 TP38.1
NetD9_1: D9.1 IC4.1 R63.1 TP40.1
NetD10_EFUSE0_2: D10_EFUSE0.2 R72_EFUSE0.1
NetD10_EFUSE1_2: D10_EFUSE1.2 R72_EFUSE1.1
NetD10_EFUSE2_2: D10_EFUSE2.2 R72_EFUSE2.1
NetD10_EFUSE3_2: D10_EFUSE3.2 R72_EFUSE3.1
NetD26_2: D26.2 R75.2
NetD27_2: D27.2 R76.2
NetD28_2: D28.2 R77.2
NetD29_2: D29.2 R78.2
NetF9_1: F9.1 U5.3 U5.8 U5.13 U5.18 U5.23 U5.28 U5.33 U5.38
NetF11_1: F11.1 J5.1
NetPS2_6: PS2.6 R1.1
NetPS2_34: PS2.34 R2.1
NetPS3_6: PS3.6 R4.1
NetPS3_34: PS3.34 R5.1
NetR13_1: R13.1 U1.7
NetR15_1: R15.1 U1.6
NetR17_2: R17.2 U4.13
NetR18_2: R18.2 U4.14
NetR19_2: R19.2 U4.15
NetR20_2: R20.2 U4.12
NetR21_2: R21.2 U4.1
NetR22_2: R22.2 U4.5
NetR23_2: R23.2 U4.2
NetR24_2: R24.2 U4.4
NetR26_1: R26.1 R28.1 TP30.1
NetR72_EFUSE0_2: R72_EFUSE0.2 TP43_EFUSE0.1 U6_EFUSE0.5
NetR72_EFUSE1_2: R72_EFUSE1.2 TP43_EFUSE1.1 U6_EFUSE1.5
NetR72_EFUSE2_2: R72_EFUSE2.2 TP43_EFUSE2.1 U6_EFUSE2.5
NetR72_EFUSE3_2: R72_EFUSE3.2 TP43_EFUSE3.1 U6_EFUSE3.5
NetR73_EFUSE0_1: R73_EFUSE0.1 U6_EFUSE0.7
NetR73_EFUSE1_1: R73_EFUSE1.1 U6_EFUSE1.7
NetR73_EFUSE2_1: R73_EFUSE2.1 U6_EFUSE2.7
NetR73_EFUSE3_1: R73_EFUSE3.1 U6_EFUSE3.7
NetR74_EFUSE0_1: R74_EFUSE0.1 U6_EFUSE0.6
NetR74_EFUSE1_1: R74_EFUSE1.1 U6_EFUSE1.6
NetR74_EFUSE2_1: R74_EFUSE2.1 U6_EFUSE2.6
NetR74_EFUSE3_1: R74_EFUSE3.1 U6_EFUSE3.6
OUT3_EFUSE1: D12.2 J4.1 U6_EFUSE1.12
OUT4_EFUSE1: D39.2 J12.1 U6_EFUSE1.9
OUT4_EFUSE3: D16.2 J8.1 U6_EFUSE3.9
"Pico UART0 Rx": R14.2 U5.22
"Pico UART0 Tx": R12.2 U5.21
PICO_3V3: D6.2 U5.36
PICO_VSYS: C30.1 C31.1 D7.1 TP34.1 U5.39
"POE SW PWR CM": C24.1 R5.2 R21.1 TP25.1
POE_OUT_1: D33.2 J11.1 U6_EFUSE0.1
POE_OUT_2: D34.2 J11.3 U6_EFUSE0.4
POE_OUT_3: D35.2 J11.5 U6_EFUSE0.12
POE_OUT_4: D36.2 J11.7 U6_EFUSE0.9
POE_OUT_5: D37.2 J11.9 U6_EFUSE1.1
POE_OUT_6: D38.2 J11.11 U6_EFUSE1.4
PSPS_IN_PROT: C19.1 C20.1 C21.1 C22.1 C23.1 F4.2 PS3.1 TP23.1
RED_EN: D28.1 IC7.1 R66.1 R67.1 U5.20
RED_LED_LOWSIDE: IC7.3 J8.4
RS_485_N: D15.2 R15.2
RS_485_P: D14.2 J5.2 R13.2
"TEMP SENSE 1": R23.1 TP27.1 U2.2
"TEMP SENSE 2": R24.1 TP28.1 U3.2
"UART RX": R10.2 R12.1 U1.1
"UART TX": R11.1 R14.1 R16.1 U1.2 U1.3 U1.4
UART_DIR: R11.2 U5.29
YELLOW_EN: D27.1 IC6.1 R64.1 R65.1 U5.19
YELLOW_LED_LOWSIDE: IC6.3 J8.3
pads on no net: D20.A D20.K D21.A D21.K D22.A D22.K D23.1 D24.1 D25.1 D31.A D31.K D32.1 J2.15 J2.16 J2.18 J2.20 J2.22 J2.32 J3.15 J3.16 J3.18 J3.22 J3.32 J4.2 J6.Un1 R17.1 U5.15 U5.16 U5.35 U5.37 U5.40
copper on no net:
  other v1: 4332.28,393.7 4332.28,866.14 11456.69,1299.21 7878.42,1640.99 11456.69,2125.98 7878.42,2231.54 6291.34,2403.15 7118.11,2403.15 5228.67,2716.16 5228.67,3070.49 6970.08,3818.9 6970.08,4173.23 6261.42,5118.11 6261.42,5826.77
  other v2: 5320.35,3822.61 5072.31,4192.68

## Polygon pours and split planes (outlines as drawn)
GND on F.Cu "F.Cu-GND-1" (solid, remove dead copper, pour order 73): 6264.96,165.61 214.96,165.61 214.96,4615.61 6264.96,4615.61
no net on F.Cu "F.Cu-/V_batt+ PROT" (solid, remove dead copper, pour order 60): 5259.45,489.63 4245.67,489.63 4048.82,292.78 1312.6,292.78 1194.49,401.05 1194.49,184.51 4078.35,184.51 4314.57,420.73 4619.69,420.73 4855.91,184.51 5259.45,174.67
no net on F.Cu "F.Cu-/i3_Vin" (solid, remove dead copper, pour order 62): 5259.45,597.9 4846.06,597.9 4619.69,775.06 4137.4,775.06 4029.13,873.49 4029.13,1217.98 3861.81,1217.98 3655.12,1030.97 3537.01,1030.97 3537.01,942.38 3773.23,735.69 3960.24,735.69 3989.76,706.16 4137.4,656.95 4580.31,656.95 4787.01,489.63 5259.45,489.63
no net on F.Cu "F.Cu-/COMP PWR OUT PROT" (solid, remove dead copper, pour order 70): 3879.53,2121.52 3879.53,2243.57 4206.3,2243.57 4237.8,2200.26 4237.8,2003.41 4332.28,1999.47 4332.28,2357.74 3588.19,2357.74 3588.19,1983.72 3714.17,1983.72
no net on F.Cu "F.Cu-/SWITCH PWR OUT PROT" (solid, remove dead copper, pour order 67): 3428.74,1227.82 3428.74,1552.62 3517.32,1601.83 3704.33,1601.83 3802.76,1680.57 4222.05,1680.57 4340.16,1840.02 4481.89,1840.02 4481.89,1680.57 4383.46,1552.62 4383.46,1483.72 4285.04,1483.72 4206.3,1546.72 3842.13,1552.62 3704.33,1434.51 3704.33,1336.09 3704.33,1257.35 3664.96,1227.82
no net on F.Cu "F.Cu-/LIGHT BANK A PROT SW" (solid, remove dead copper, pour order 49): 1696.46,4239.63 1509.45,4052.62 1509.45,3479.79 1367.72,3345.93 1342.13,3314.43 1342.13,3204.2 1320.47,3180.57 1320.47,2975.85 1292.91,2936.48 1150,2936.56 1090,2996.56 1086.22,3521.12 1253.54,3521.12 1302.76,3570.34 1302.76,4101.83 1489.76,4288.84 1489.76,4416.79 1696.46,4416.79
no net on F.Cu "F.Cu-/5V Intermediate" (solid, remove dead copper, pour order 61): 3222.05,1208.13 3428.74,1208.13 3428.74,1030.97 3773.23,735.69 3960.24,735.69 3989.76,706.16 3989.76,341.99 3960.24,312.46 3537.01,312.46 3487.8,361.68 3487.8,558.53 3222.05,824.27
no net on F.Cu "F.Cu-/48V PWR" (solid, remove dead copper, pour order 32): 2070.47,1080.18 1942.52,883.33 1943.5,686.48 1460.24,686.48 1460.24,1090.02 1499.61,1149.08 1499.61,1523.09 2070.47,1523.09
no net on F.Cu "F.Cu-/15v PWR" (solid, remove dead copper, pour order 48): 2100,3649.08 2226.97,3881.36 2225.98,4078.21 2709.25,4078.21 2709.25,3611.56 2670,3611.56 2669.88,3241.6 2099.02,3241.6
PSPS_IN_PROT on F.Cu "F.Cu-/PSPS_IN_PROT" (solid, remove dead copper, pour order 52): 1903.15,2369.55 1662.99,2369.55 1662.99,2221.91 1584.25,2147.11 1584.25,1930.57 1548.82,1857.74 1548.82,1708.13 2017.32,1708.13 2017.32,1834.12 2344.09,1834.12 2344.09,1708.13 2611.81,1708.13 2611.81,1985.69 2001.57,1985.69 1903.15,2221.91
+48V on F.Cu "F.Cu-/CPS_IN_PROT" (solid, remove dead copper, pour order 55): 1657.09,2389.24 2592.13,2389.24 2592.13,3117.58 2119.69,3117.58 2119.69,3042.78 2060.63,2969.94 1588.19,2967.98 1588.19,2849.86 2060.63,2849.86 2198.43,2733.72 2198.43,2558.53 1657.09,2558.53
no net on F.Cu "F.Cu-/V_batt+" (solid, remove dead copper, pour order 41): 2374.85,305 1233.86,305 1233.86,676.64 2375.59,676.64
no net on F.Cu "F.Cu-/V_batt+ PROT-1" (solid, remove dead copper, pour order 33): 564.57,853.8 741.73,676.64 1233.86,676.64 1233.86,184.51 466.14,184.51 -6.3,676.64 0,1146.56 564.57,1146.56
no net on F.Cu "F.Cu-/LIGHT BANK B PROT SW" (solid, remove dead copper, pour order 34): 1290.94,4285.89 1292.91,3570.34 1253.54,3530.97 1086.22,3530.97 1086.22,4416.79 1292.91,4416.79
no net on F.Cu "F.Cu-/LIGHT BANK B PROT" (solid, remove dead copper, pour order 35): 1076.38,3530.97 968.11,3530.97 879.53,3452.23 880,2916.56 968.11,2816.56 968.11,2615.61 1046.85,2527.03 1194.49,2527.03 1194.49,2221.91 1030,2225.56 751.57,2507.35 751.57,2782.94 643.31,2910.89 643.31,3649.08 879.53,3904.98 879.53,4042.78 1076.38,4042.78
no net on F.Cu "F.Cu-/V_batt+ PROT SW" (solid, remove dead copper, pour order 42): 741.73,2782.94 741.73,2507.35 1030,2213.56 1135.43,2212.07 1204.33,2280.97 1204.33,2517.19 1273.23,2586.09 1568.5,2586.09 1568.5,2202.23 1316.54,2202.23 1076.38,1956.16 1076.38,1056.56 997.64,946.56 574.41,946.56 574.41,1466.56 416.93,1606.56 416.93,2901.05 643.31,2901.05
no net on F.Cu "F.Cu-/LIGHT BANK A PROT" (solid, remove dead copper, pour order 43): 1090,2996.56 1194.49,2886.56 1194.49,2536.87 1046.85,2536.87 977.95,2615.61 977.95,2826.56 889.37,2926.56 889.37,3452.23 968.11,3521.12 1076.38,3521.12
no net on F.Cu "F.Cu-/15V Aux PWR OUT PROT" (solid, remove dead copper, pour order 66): 3802.76,1680.57 3802.89,1819.09 4044.88,2030.97 4044.88,2243.57 3879.53,2243.57 3879.53,2121.52 3572.44,1865.61 3572.44,1601.83 3704.33,1601.83
GND on F.Cu "F.Cu-GND" (solid, remove dead copper, pour order 69): 3580.31,251.44 2689.57,243.57 2690.55,735.69 3580.31,743.57
GND on In2.Cu "In2.Cu-GND-1" (solid, remove dead copper, pour order 74): 6264.96,165.61 214.96,165.61 214.96,4615.61 6264.96,4615.61
no net on In2.Cu "In2.Cu-/48V Aux PWR OUT PROT" (solid, remove dead copper, pour order 64): 4462.2,499.47 4462.2,647.11 4462.2,794.75 4462.2,1040.81 4806.69,1040.81 4806.69,942.38 4777.17,912.86 4777.17,499.47 4639.37,499.47
no net on In2.Cu "In2.Cu-/V_batt+ PROT" (solid, remove dead copper, pour order 59): 5259.45,489.63 4245.67,489.63 4048.82,292.78 1312.6,292.78 1194.49,401.05 1194.49,184.51 4078.35,184.51 4314.57,420.73 4619.69,420.73 4855.91,184.51 5259.45,174.67
no net on In2.Cu "In2.Cu-/48V PWR-1" (solid, remove dead copper, pour order 57): 2031.1,1237.66 2798.82,1237.66 2877.56,1306.56 2877.56,1532.94 3153.15,1532.94 3153.15,1385.3 3320.47,1227.82 4117.72,1227.82 4235.83,1109.71 4235.83,775.06 4029.13,775.06 4029.13,1030.97 2434.65,1030.97 2346.06,1030.97 2031.1,1030.97
GND on In2.Cu "In2.Cu-GND-3" (solid, remove dead copper, pour order 47): 314.96,1215.61 314.96,1865.61 464.96,2015.61 734.96,2015.61 1104.96,1655.61 1104.96,1215.61
GND on In2.Cu "In2.Cu-GND-2" (solid, remove dead copper, pour order 23): 3354.96,4585.61 3354.96,2415.61 4514.96,2415.61 4514.96,4585.61
PSPS_IN_PROT on In2.Cu "In2.Cu-/PSPS_IN_PROT" (solid, remove dead copper, pour order 51): 1903.15,2369.55 1662.99,2369.55 1662.99,2221.91 1584.25,2147.11 1584.25,1930.57 1548.82,1857.74 1548.82,1708.13 2017.32,1708.13 2017.32,1834.12 2344.09,1834.12 2344.09,1708.13 2611.81,1708.13 2611.81,1985.69 2001.57,1985.69 1903.15,2221.91
no net on In2.Cu "In2.Cu-/V_batt+ PROT-1" (solid, remove dead copper, pour order 31): 564.57,853.8 741.73,676.64 1233.86,676.64 1233.86,184.51 466.14,184.51 -6.3,676.64 0,1146.56 564.57,1146.56
+48V on In2.Cu "In2.Cu-/CPS_IN_PROT" (solid, remove dead copper, pour order 54): 1657.09,2389.24 2592.13,2389.24 2592.13,3117.58 2119.69,3117.58 2119.69,3042.78 2060.63,2969.94 1588.19,2967.98 1588.19,2849.86 2060.63,2849.86 2198.43,2733.72 2198.43,2558.53 1657.09,2558.53
no net on In2.Cu "In2.Cu-/V_batt+ PROT SW" (solid, remove dead copper, pour order 40): 741.73,2782.94 741.73,2507.35 1030,2213.56 1135.43,2212.07 1204.33,2280.97 1204.33,2517.19 1273.23,2586.09 1568.5,2586.09 1568.5,2202.23 1316.54,2202.23 1076.38,1956.16 1076.38,1056.56 997.64,946.56 574.41,946.56 574.41,1466.56 416.93,1606.56 416.93,2901.05 643.31,2901.05
no net on In2.Cu "In2.Cu-/V_batt+" (solid, remove dead copper, pour order 39): 2374.61,184.51 1233.86,184.51 1233.86,676.64 2375.59,676.64
no net on In2.Cu "In2.Cu-/48V PWR" (solid, remove dead copper, pour order 30): 2070.47,1080.18 1942.52,883.33 1943.5,686.48 1460.24,686.48 1460.24,1090.02 1499.61,1149.08 1499.61,1523.09 2070.47,1523.09
no net on In2.Cu "In2.Cu-/15v PWR" (solid, remove dead copper, pour order 46): 2100,3649.08 2226.97,3881.36 2225.98,4078.21 2709.25,4078.21 2709.25,3611.56 2670,3611.56 2669.88,3241.6 2099.02,3241.6
GND on In2.Cu "In2.Cu-GND" (solid, remove dead copper, pour order 71): 3580.31,251.44 2689.57,243.57 2690.55,735.69 3580.31,743.57
GND on B.Cu "B.Cu-GND-1" (solid, remove dead copper, pour order 77): 6354.96,59.06 69.96,59.06 69.96,4724.06 6354.96,4724.06
no net on B.Cu "B.Cu-/48V Aux PWR OUT PROT" (solid, remove dead copper, pour order 63): 4462.2,499.47 4462.2,647.11 4462.2,794.75 4462.2,1040.81 4806.69,1040.81 4806.69,942.38 4777.17,912.86 4777.17,499.47 4639.37,499.47
no net on B.Cu "B.Cu-/V_batt+ PROT" (solid, remove dead copper, pour order 58): 5259.45,489.63 4245.67,489.63 4048.82,292.78 1312.6,292.78 1194.49,401.05 1194.49,184.51 4078.35,184.51 4314.57,420.73 4619.69,420.73 4855.91,184.51 5259.45,174.67
no net on B.Cu "B.Cu-/COMP PWR OUT PROT-1" (solid, remove dead copper, pour order 28): 5268.9,3892.82 4985,3892.82 4845,3891.56 4430,3891.56 4155,3626.56 4155,2265.61 4020,2265.61 4020,3706.56 4360,4031.56 4825,4031.56 4950,4159.2 5268.9,4160.77
no net on B.Cu "B.Cu-/V_batt+" (solid, remove dead copper, pour order 36): 2374.61,184.51 1233.86,184.51 1233.86,676.64 2375.59,676.64
no net on B.Cu "B.Cu-/15v PWR-1" (solid, remove dead copper, pour order 29): 3223.31,1625.49 3170.87,1576.56 2980,1576.56 2935,1626.56 2935,3176.56 2870,3241.56 2655,3241.56 2655,3616.56 3020,3616.56 3223.31,3455.49
no net on B.Cu "B.Cu-/48V PWR-1" (solid, remove dead copper, pour order 56): 2031.1,1237.66 2798.82,1237.66 2877.56,1306.56 2877.56,1532.94 3153.15,1532.94 3153.15,1385.3 3320.47,1227.82 4117.72,1227.82 4235.83,1109.71 4235.83,775.06 4029.13,775.06 4029.13,1030.97 2434.65,1030.97 2346.06,1030.97 2031.1,1030.97
GND on B.Cu "B.Cu-GND-2" (solid, remove dead copper, pour order 22): 3354.96,4585.61 3354.96,2415.61 4304.96,2419.06 4304.96,4585.61
no net on B.Cu "B.Cu-/LIGHT BANK B PROT" (solid, remove dead copper, pour order 27): 1076.38,3530.97 968.11,3530.97 879.53,3452.23 880,2916.56 968.11,2816.56 968.11,2615.61 1046.85,2527.03 1194.49,2527.03 1194.49,2221.91 1030,2225.56 751.57,2507.35 751.57,2782.94 643.31,2910.89 643.31,3649.08 879.53,3904.98 879.53,4042.78 1076.38,4042.78
no net on B.Cu "B.Cu-/COMP PWR OUT PROT" (solid, remove dead copper, pour order 68): 3879.53,2121.52 3879.53,2243.57 4206.3,2243.57 4237.8,2200.26 4237.8,2003.41 4332.28,1999.47 4332.28,2357.74 3588.19,2357.74 3588.19,1983.72 3714.17,1983.72
no net on B.Cu "B.Cu-/LIGHT BANK B PROT SW" (solid, remove dead copper, pour order 26): 1290.94,4285.89 1292.91,3570.34 1253.54,3530.97 1086.22,3530.97 1086.22,4416.79 1292.91,4416.79
no net on B.Cu "B.Cu-/LIGHT BANK A PROT SW" (solid, remove dead copper, pour order 45): 1696.46,4239.63 1509.45,4052.62 1509.45,3479.79 1367.72,3345.93 1342.13,3314.43 1342.13,3204.2 1320.47,3180.57 1320.47,2975.85 1292.91,2936.48 1150,2936.56 1090,2996.56 1086.22,3521.12 1253.54,3521.12 1302.76,3570.34 1302.76,4101.83 1489.76,4288.84 1489.76,4416.79 1696.46,4416.79
no net on B.Cu "B.Cu-/LIGHT BANK A PROT" (solid, remove dead copper, pour order 38): 1090,2996.56 1194.49,2886.56 1194.49,2536.87 1046.85,2536.87 977.95,2615.61 977.95,2826.56 889.37,2926.56 889.37,3452.23 968.11,3521.12 1076.38,3521.12
no net on B.Cu "B.Cu-/15V Aux PWR OUT PROT" (solid, remove dead copper, pour order 65): 3802.76,1680.57 3802.89,1819.09 4044.88,2030.97 4044.88,2243.57 3879.53,2243.57 3879.53,2121.52 3572.44,1865.61 3572.44,1601.83 3704.33,1601.83
PSPS_IN_PROT on B.Cu "B.Cu-/PSPS_IN_PROT" (solid, remove dead copper, pour order 50): 1903.15,2369.55 1662.99,2369.55 1662.99,2221.91 1584.25,2147.11 1584.25,1930.57 1548.82,1857.74 1548.82,1708.13 2017.32,1708.13 2017.32,1834.12 2344.09,1834.12 2344.09,1708.13 2611.81,1708.13 2611.81,1985.69 2001.57,1985.69 1903.15,2221.91
no net on B.Cu "B.Cu-/V_batt+ PROT-1" (solid, remove dead copper, pour order 25): 564.57,853.8 741.73,676.64 1233.86,676.64 1233.86,184.51 466.14,184.51 -6.3,676.64 0,1146.56 564.57,1146.56
+48V on B.Cu "B.Cu-/CPS_IN_PROT" (solid, remove dead copper, pour order 53): 1657.09,2389.24 2592.13,2389.24 2592.13,3117.58 2119.69,3117.58 2119.69,3042.78 2060.63,2969.94 1588.19,2967.98 1588.19,2849.86 2060.63,2849.86 2198.43,2733.72 2198.43,2558.53 1657.09,2558.53
no net on B.Cu "B.Cu-/V_batt+ PROT SW" (solid, remove dead copper, pour order 37): 741.73,2782.94 741.73,2507.35 1030,2213.56 1135.43,2212.07 1204.33,2280.97 1204.33,2517.19 1273.23,2586.09 1568.5,2586.09 1568.5,2202.23 1316.54,2202.23 1076.38,1956.16 1076.38,1056.56 997.64,946.56 574.41,946.56 574.41,1466.56 416.93,1606.56 416.93,2901.05 643.31,2901.05
no net on B.Cu "B.Cu-/48V PWR" (solid, remove dead copper, pour order 24): 2070.47,1080.18 1942.52,883.33 1943.5,686.48 1460.24,686.48 1460.24,1090.02 1499.61,1149.08 1499.61,1523.09 2070.47,1523.09
no net on B.Cu "B.Cu-/15v PWR" (solid, remove dead copper, pour order 44): 2100,3649.08 2226.97,3881.36 2225.98,4078.21 2709.25,4078.21 2709.25,3611.56 2670,3611.56 2669.88,3241.6 2099.02,3241.6
GND on B.Cu "B.Cu-GND" (solid, remove dead copper, pour order 72): 3580.31,251.44 2689.57,243.57 2690.55,735.69 3580.31,743.57
GND on In1.Cu "In1.Cu-GND" (solid, remove dead copper, pour order 76): 6264.96,165.61 214.96,165.61 214.96,4615.61 6264.96,4615.61
GND on In1.Cu "In1.Cu-GND-1" (solid, remove dead copper, pour order 21): 3354.96,4585.61 3354.96,2415.61 4514.96,2415.61 4514.96,4585.61

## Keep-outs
F.Cu:
  region: 5835,3511.56 5605,3511.56 5605,4146.56 5835,4146.56
  region: 5590,2971.56 5590,1021.56 5535,966.56 5030,966.56 4980,1021.56 4980,2976.56 5020,3026.56 5545,3026.56
  region: 4435,2591.56 4205,2591.56 4205,3126.56 4435,3126.56
  region: 5875,171.56 5264.69,171.56 5264.69,481.56 5505,481.56
In1.Cu:
  region: 5875,171.56 5264.69,171.56 5264.69,481.56 5505,481.56
In2.Cu:
  region: 5835,3511.56 5605,3511.56 5605,4146.56 5835,4146.56
  region: 5590,2971.56 5590,1021.56 5535,966.56 5030,966.56 4980,1021.56 4980,2976.56 5020,3026.56 5545,3026.56
  region: 4435,2591.56 4205,2591.56 4205,3126.56 4435,3126.56
  region: 5875,171.56 5264.69,171.56 5264.69,481.56 5505,481.56
B.Cu:
  region: 5835,3511.56 5605,3511.56 5605,4146.56 5835,4146.56
  region: 5590,2971.56 5590,1021.56 5535,966.56 5030,966.56 4980,1021.56 4980,2976.56 5020,3026.56 5545,3026.56
  region: 4435,2591.56 4205,2591.56 4205,3126.56 4435,3126.56
  region: 5875,171.56 5264.69,171.56 5264.69,481.56 5505,481.56
Edge.Cuts:
  circle w10: c4464.5,2355.17 r196.85
  lines w0: 2.56,662.26 475,189.82 4070.8,189.82 4307.02,426.04 4621.98,426.04 4858.2,189.82 5671.85,189.82 5908.07,426.04 5908.07,4284.31 5671.85,4520.53 4858.2,4520.53 4621.98,4284.31 4307.02,4284.31 4070.8,4520.53 475,4520.53 2.56,4048.09 2.56,2906.36 396.26,2512.65 396.26,2197.69 2.56,1803.99 2.56,662.26
  lines w10: 2.56,662.26 475,189.82 4070.8,189.82 4307.02,426.04 4621.98,426.04 4858.2,189.82 5671.85,189.82 5908.07,426.04 5908.07,4284.31 5671.85,4520.53 4858.2,4520.53 4621.98,4284.31 4307.02,4284.31 4070.8,4520.53 475,4520.53 2.56,4048.09 2.56,2906.36 396.26,2512.65 396.26,2197.69 2.56,1803.99 2.56,662.26

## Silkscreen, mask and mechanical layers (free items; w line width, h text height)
F.SilkS:
  text "14" at 4938.58,3760.11 h39.37
  text "13" at 5013.39,3759.91 h39.37
  text "12" at 5092.13,3760.11 h39.37
  text "11" at 5170.87,3760.22 h39.37
  text "TP:" at 4852.33,3708.9 h39.37
  text "RESET" at 4471.86,3602.76 h59.06
  text "6" at 4867.72,3574.98 h39.37
  text "7" at 4946.46,3574.98 h39.37
  text "8" at 5025.2,3574.87 h39.37
  text "9" at 5111.81,3575.07 h39.37
  text "10" at 5170.87,3574.87 h39.37
  text "lantMap" at 1913.82,2403.38 h98.43
  text "P" at 1777.17,2325.88 h157.48
  text "AUX SW" at 3528.19,2303.83 h78.74
  text "V0.3" at 2470.08,2173.3 h39.37
  text "3D" at 2170.87,2167.16 h157.48
B.SilkS:
  text "lantMap" at 5210.24,3466.85 h118.11
  text "P" at 5380.24,3387.42 h196.85
  text "3D" at 4575.24,3379.72 h196.85
  text "System Management Board V0.3 / 7-30-2024 -- M. Funderburk, C. Nichols / Precision Sustainable Agriculture" at 5355.24,3285.57 h39.37

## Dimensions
2.56,662.26 to 5910,661.56 on Eco1.User
5671.85,4520.53 to 5668.9,2965.02 on Eco1.User
5671.85,4520.53 to 5671.85,189.82 on Eco1.User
